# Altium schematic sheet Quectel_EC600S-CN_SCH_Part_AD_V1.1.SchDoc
size A1
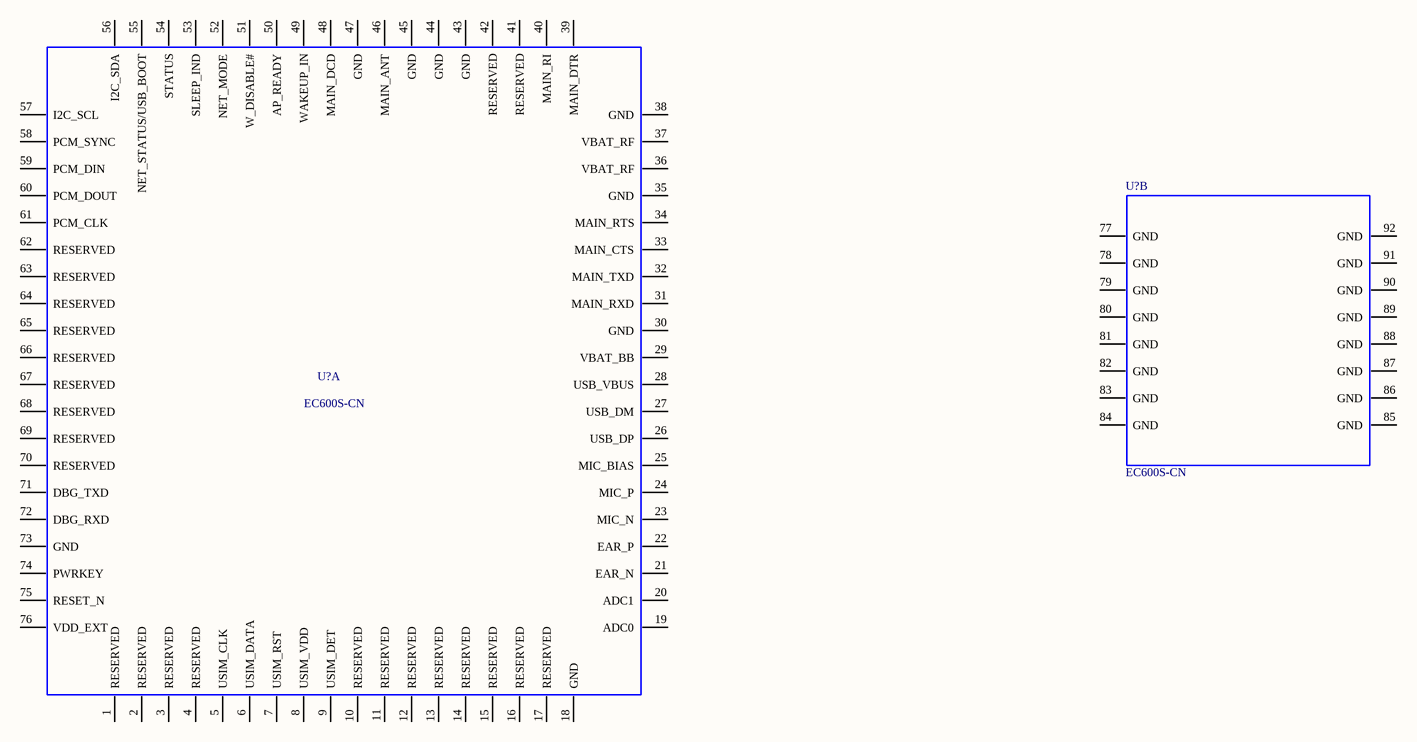
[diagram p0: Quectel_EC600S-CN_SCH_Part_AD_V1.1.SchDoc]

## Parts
(Parts that share a designator on the sheet are numbered #1, #2 ... from top to bottom, then left to right.)
U?#1  EC600S-CN  (part B of 2)
U?#2  EC600S-CN  (part A of 2)

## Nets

Not connected (* = marked no-connect by the designer): U?#1 77(GND) 78(GND) 79(GND) 80(GND) 81(GND) 82(GND) 83(GND) 84(GND) 85(GND) 86(GND) 87(GND) 88(GND) 89(GND) 90(GND) 91(GND) 92(GND); U?#2 1(RESERVED) 2(RESERVED) 3(RESERVED) 4(RESERVED) 5(USIM_CLK) 6(USIM_DATA) 7(USIM_RST) 8(USIM_VDD) 9(USIM_DET) 10(RESERVED) 11(RESERVED) 12(RESERVED) 13(RESERVED) 14(RESERVED) 15(RESERVED) 16(RESERVED) 17(RESERVED) 18(GND) 19(ADC0) 20(ADC1) 21(EAR_N) 22(EAR_P) 23(MIC_N) 24(MIC_P) 25(MIC_BIAS) 26(USB_DP) 27(USB_DM) 28(USB_VBUS) 29(VBAT_BB) 30(GND) 31(MAIN_RXD) 32(MAIN_TXD) 33(MAIN_CTS) 34(MAIN_RTS) 35(GND) 36(VBAT_RF) 37(VBAT_RF) 38(GND) 39(MAIN_DTR) 40(MAIN_RI) 41(RESERVED) 42(RESERVED) 43(GND) 44(GND) 45(GND) 46(MAIN_ANT) 47(GND) 48(MAIN_DCD) 49(WAKEUP_IN) 50(AP_READY) 51(W_DISABLE#) 52(NET_MODE) 53(SLEEP_IND) 54(STATUS) 55(NET_STATUS/USB_BOOT) 56(I2C_SDA) 57(I2C_SCL) 58(PCM_SYNC) 59(PCM_DIN) 60(PCM_DOUT) 61(PCM_CLK) 62(RESERVED) 63(RESERVED) 64(RESERVED) 65(RESERVED) 66(RESERVED) 67(RESERVED) 68(RESERVED) 69(RESERVED) 70(RESERVED) 71(DBG_TXD) 72(DBG_RXD) 73(GND) 74(PWRKEY) 75(RESET_N) 76(VDD_EXT)

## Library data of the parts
U?#1 U?#2 = EC600S-CN: EC600S-CN module 76LCC 16LGA 22.9x23.9mm H2.5mm RO; Manufacturer: Quectel; Geometry.Height: 2.5mm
